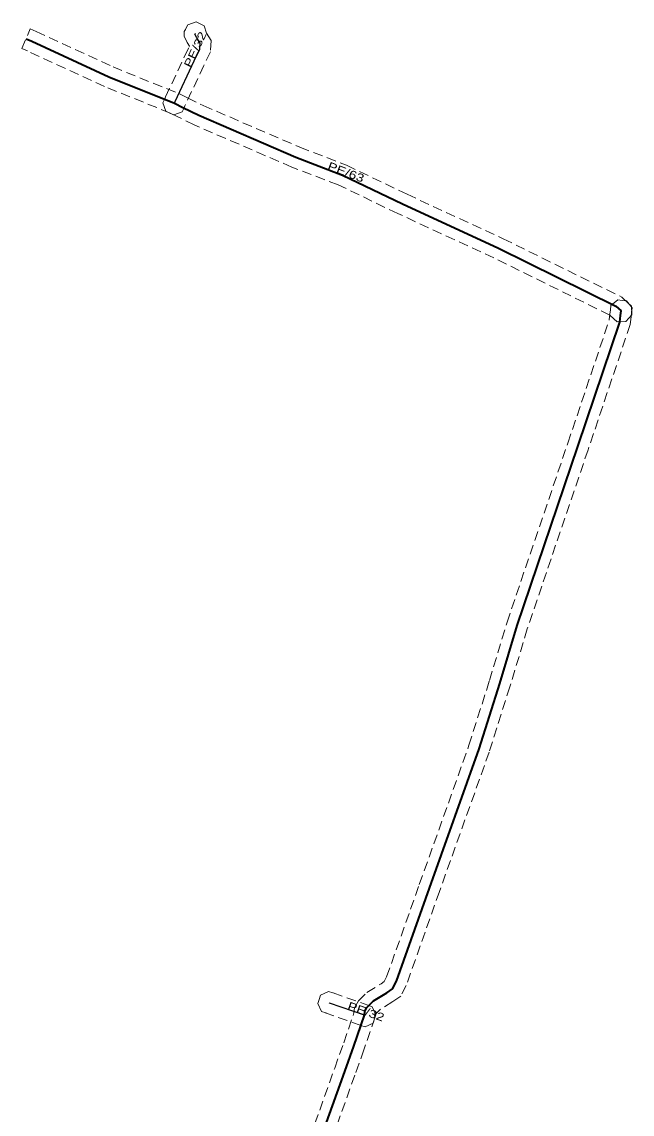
# Model space of a CAD drawing. Extents: x -601345 to -601001, y -1004225 to -1003815.
# Drawn here: x -601222.9 to -601165.6, y -1003917.9 to -1003815.5 of the extents above; entities that cross this region are included whole.
import ezdxf

# ---------------------------------------------------------------- set-up
doc = ezdxf.new("R2010")
doc.units = 0
doc.header["$LTSCALE"] = 0.3
doc.linetypes.add('MEDIUM_DASHED', pattern=[4.5, 3, -1.5])
doc.layers.add('1', color=7, linetype='MEDIUM_DASHED', lineweight=13)
doc.layers.add('24', color=7, linetype='Continuous', lineweight=25)
doc.layers.add('30', color=7, linetype='Continuous')

msp = doc.modelspace()

# ---------------------------------------------------------------- linework, layer by layer
at = {"layer": '1'}
for points in [[(-601222.338, -1003818.203), (-601222.856, -1003817.979), (-601222.075, -1003816.138), (-601221.522, -1003816.377), (-601214.303, -1003819.702), (-601208.145, -1003822.196), (-601207.335, -1003822.593), (-601205.851, -1003823.321), (-601196.783, -1003827.234), (-601192.404, -1003828.911), (-601186.743, -1003831.636), (-601177.739, -1003835.797), (-601166.599, -1003841.286), (-601166.004, -1003841.833), (-601165.699, -1003842.113), (-601165.663, -1003842.941), (-601165.943, -1003843.246), (-601166.223, -1003843.551), (-601167.051, -1003843.587), (-601167.356, -1003843.307), (-601167.741, -1003842.954), (-601178.601, -1003837.603), (-601187.597, -1003833.444), (-601193.196, -1003830.749), (-601197.537, -1003829.086), (-601206.689, -1003825.139), (-601208.217, -1003824.389), (-601208.963, -1003824.022), (-601215.097, -1003821.538)], [(-601205.777, -1003815.838), (-601205.543, -1003816.527), (-601205.111, -1003817.22), (-601205.174, -1003818.298), (-601205.791, -1003819.564), (-601207.566, -1003823.356), (-601207.646, -1003823.529), (-601207.82, -1003823.905), (-601208.598, -1003824.191), (-601208.974, -1003824.017), (-601209.35, -1003823.843), (-601209.636, -1003823.065), (-601209.462, -1003822.689), (-601209.38, -1003822.512), (-601207.595, -1003818.702), (-601207.148, -1003817.782), (-601207.145, -1003817.738), (-601207.351, -1003817.407), (-601207.521, -1003817.066), (-601207.625, -1003816.857), (-601207.626, -1003816.389), (-601207.522, -1003816.179), (-601207.488, -1003816.11), (-601207.305, -1003815.738), (-601206.521, -1003815.472), (-601206.149, -1003815.655)], [(-601190.682, -1003909.671), (-601191.073, -1003909.533), (-601194.332, -1003908.383), (-601194.368, -1003908.37), (-601194.759, -1003908.233), (-601195.118, -1003907.487), (-601194.98, -1003907.096), (-601194.843, -1003906.705), (-601194.097, -1003906.346), (-601193.706, -1003906.484), (-601193.668, -1003906.497), (-601190.407, -1003907.647), (-601190.016, -1003907.785), (-601189.659, -1003908.532), (-601189.797, -1003908.923), (-601189.935, -1003909.314)]]:
    msp.add_lwpolyline(points, close=True, dxfattribs=at)
msp.add_lwpolyline([(-601195.383, -1003918.746), (-601193.522, -1003913.534), (-601192.674, -1003911.16), (-601191.719, -1003908.363), (-601191.657, -1003907.881), (-601191.303, -1003907.247), (-601190.503, -1003906.46), (-601189.174, -1003905.631), (-601188.884, -1003905.436), (-601188.661, -1003904.995), (-601185.592, -1003896.325), (-601180.938, -1003883.281), (-601179.015, -1003877.205), (-601177.372, -1003871.755), (-601171.667, -1003854.95), (-601167.781, -1003843.391), (-601167.722, -1003842.88), (-601167.673, -1003842.455), (-601167.626, -1003842.044), (-601166.977, -1003841.529), (-601166.565, -1003841.577), (-601166.154, -1003841.624), (-601165.639, -1003842.273), (-601165.687, -1003842.685), (-601165.736, -1003843.11), (-601165.819, -1003843.829), (-601169.773, -1003855.59), (-601175.468, -1003872.365), (-601177.105, -1003877.795), (-601179.042, -1003883.919), (-601183.708, -1003896.995), (-601186.819, -1003905.785), (-601187.336, -1003906.804), (-601188.086, -1003907.309), (-601189.257, -1003908.04), (-601189.697, -1003908.473), (-601189.723, -1003908.519), (-601189.761, -1003908.817), (-601190.786, -1003911.82), (-601191.638, -1003914.206), (-601193.497, -1003919.414)], dxfattribs=at)
at = {"layer": '24', "lineweight": 40}
for points in [[(-601222.465, -1003817.059), (-601221.93, -1003817.29), (-601214.7, -1003820.62), (-601208.554, -1003823.109), (-601207.776, -1003823.491), (-601206.27, -1003824.23), (-601197.16, -1003828.16), (-601192.8, -1003829.83), (-601187.17, -1003832.54), (-601178.17, -1003836.7), (-601167.17, -1003842.12), (-601166.68, -1003842.57)], [(-601194.44, -1003919.08), (-601192.58, -1003913.87), (-601191.73, -1003911.49), (-601190.74, -1003908.59), (-601190.69, -1003908.2), (-601190.5, -1003907.86), (-601189.88, -1003907.25), (-601188.63, -1003906.47), (-601188.11, -1003906.12), (-601187.74, -1003905.39), (-601184.65, -1003896.66), (-601179.99, -1003883.6), (-601178.06, -1003877.5), (-601176.42, -1003872.06), (-601170.72, -1003855.27), (-601166.8, -1003843.61), (-601166.729, -1003842.995), (-601166.68, -1003842.57)]]:
    msp.add_lwpolyline(points, dxfattribs=at)
at = {"layer": '24'}
for points in [[(-601208.554, -1003823.109), (-601208.473, -1003822.934), (-601206.693, -1003819.133), (-601206.161, -1003818.04), (-601206.128, -1003817.479), (-601206.477, -1003816.919), (-601206.625, -1003816.621), (-601206.591, -1003816.552)], [(-601190.74, -1003908.59), (-601194, -1003907.44), (-601194.037, -1003907.427)]]:
    msp.add_lwpolyline(points, dxfattribs=at)

# ---------------------------------------------------------------- texts
at = {"layer": '30', "width": 1.3}
for s, rotation, p in [('PE/32', 64.906, (-601207.02, -1003819.831)), ('PE/63', 339.042, (-601194.256, -1003829.272)), ('PE/32', 340.569, (-601192.388, -1003908.008))]:
    msp.add_text(s, height=0.75, rotation=rotation, dxfattribs=at).set_placement(p)

doc.saveas('drawing.dxf')
